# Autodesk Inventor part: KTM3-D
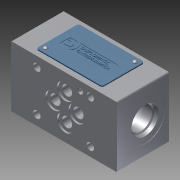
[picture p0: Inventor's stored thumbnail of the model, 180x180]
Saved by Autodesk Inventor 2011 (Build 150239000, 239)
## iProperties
Created: 2012-01
Part Number: KTM3-D
Document SubType Name: Modeling
Designer: khramov
Density: 1 g/cm^3
Author: khramov
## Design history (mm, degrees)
derived "KTM3_D_10N.iam"
node "Твердое тело1"
node "0134965.ipt:1"
sketch "3001110000.ipt:1"
sketch "0530521.ipt:1"
sketch "0530521.ipt:2"
